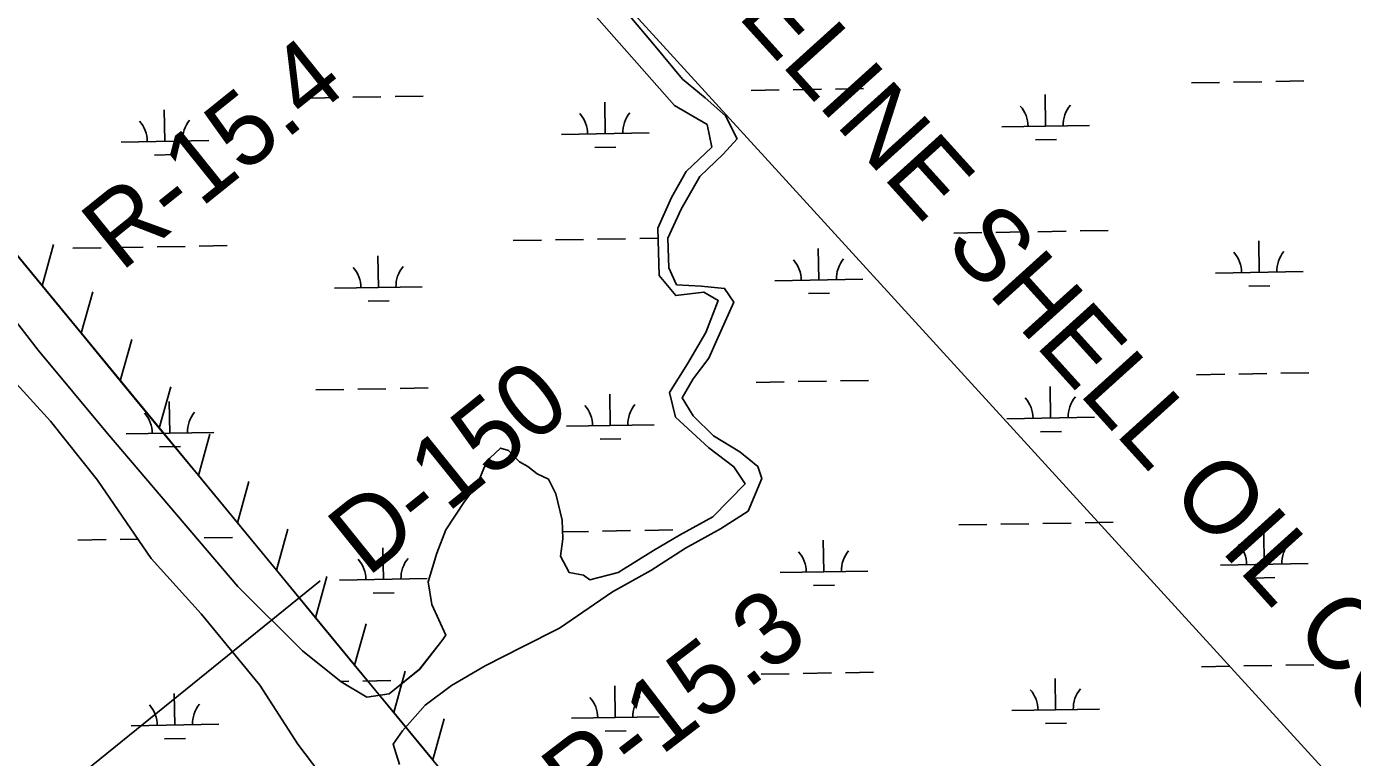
# Model space of a CAD drawing. Extents: x 3887375 to 3925618, y 296674 to 322633.
# Drawn here: x 3899931 to 3901441, y 308942 to 309775 of the extents above; entities that cross this region are included whole.
import ezdxf

# ---------------------------------------------------------------- set-up
doc = ezdxf.new("R2010")
doc.units = 0
for name, color, linetype in [('V-RIVR-EDGE', 7, 'Continuous'), ('V-RIVR-RANG', 7, 'Continuous'), ('V-RIVR-RANG-IDEN', 7, 'Continuous'), ('V-RRAP-FSHR', 7, 'Continuous'), ('V-TOPO-SHOR', 7, 'Continuous'), ('V-UTIL-IDEN', 7, 'Continuous'), ('V-UTIL-LINE', 7, 'Continuous'), ('V-WETL-SWMP', 7, 'Continuous')]:
    doc.layers.add(name, color=color, linetype=linetype)

msp = doc.modelspace()

# ---------------------------------------------------------------- linework, layer by layer
at = {"layer": 'V-RIVR-EDGE'}
msp.add_spline([(3894498, 310522.4), (3894530, 310496.1), (3894553.8, 310474.7), (3894579.9, 310451.3), (3894614.8, 310419.2), (3894633.2, 310400.7), (3894662.8, 310372.4), (3894685.1, 310353.4), (3894692.4, 310347.1), (3894709.8, 310328.1), (3894746.6, 310285.3), (3894785.8, 310252.2), (3894809.6, 310225.9), (3894830.4, 310205.4), (3894852.7, 310189.9), (3894866.7, 310171.8), (3894915.2, 310120.3), (3894950.1, 310083.7), (3894971.4, 310062.8), (3894999, 310039.4), (3895025.2, 310017), (3895052.8, 309992.7), (3895093, 309952.3), (3895110.9, 309932.8), (3895141.4, 309903.1), (3895188.9, 309855.9), (3895222.8, 309821.3), (3895255.8, 309784.3), (3895319.2, 309722.5), (3895350.7, 309688.4), (3895358.4, 309676.3), (3895364.7, 309669.4), (3895374.9, 309663.1), (3895389, 309650.4), (3895410.8, 309628.1), (3895448.5, 309583.3), (3895480.5, 309554.1), (3895503.8, 309527.8), (3895533.8, 309499.5), (3895577.4, 309454.8), (3895606.9, 309425.5), (3895653.5, 309378.8), (3895685.9, 309349.1), (3895719.8, 309314.5), (3895749.4, 309285.8), (3895790.6, 309242.5), (3895837.1, 309195.8), (3895863.7, 309164.1), (3895900, 309127.6), (3895944.1, 309081.4), (3895955.7, 309070.7), (3895974.6, 309054.6), (3896002.3, 309033.1), (3896032.8, 309003.9), (3896062.8, 308972.3), (3896082.7, 308950.4), (3896119.5, 308911.9), (3896139.3, 308892.5), (3896152, 308889.5), (3896163.1, 308883.7), (3896167.9, 308873.9), (3896170.3, 308862.3), (3896184.4, 308844.3), (3896211, 308816), (3896224.1, 308810.2), (3896236.7, 308802.4), (3896249.8, 308786.8), (3896255.6, 308776.6), (3896270.6, 308766.4), (3896280.3, 308753.2), (3896295.8, 308737.2), (3896375.3, 308661.2), (3896425.2, 308610.1), (3896464.4, 308570.6), (3896519.6, 308515.6), (3896548.7, 308483), (3896563.2, 308467.5), (3896597.6, 308430.9), (3896635.9, 308396.4), (3896666.4, 308365.7), (3896681.4, 308349.6), (3896712.4, 308320.4), (3896746.3, 308287.3), (3896777.4, 308260), (3896801.6, 308235.7), (3896820.5, 308215.3), (3896842.8, 308195.3), (3896851.5, 308181.2), (3896882.5, 308148.6), (3896918.8, 308116.4), (3896962.9, 308074.6), (3896997.8, 308033.2), (3897029.2, 307998.6), (3897042.3, 307985), (3897083.5, 307945.6), (3897107.2, 307918.3), (3897123.2, 307898.8), (3897130, 307898.8), (3897142.1, 307893), (3897146, 307882.3), (3897149.9, 307874), (3897162.9, 307860.4), (3897188.6, 307833.1), (3897229.3, 307788.8), (3897267.6, 307752.3), (3897300.5, 307715.8), (3897334.4, 307680.3), (3897361.5, 307651.1), (3897384.8, 307628.2), (3897411.4, 307599), (3897445.8, 307563.4), (3897494.3, 307516.7), (3897543.2, 307462.7), (3897584.8, 307418.4), (3897609, 307394), (3897646.8, 307355.6), (3897678.8, 307323.9), (3897715.1, 307290.3), (3897752, 307253.3), (3897767, 307236.3), (3897837.7, 307158.4), (3897886.6, 307104.4), (3897936, 307048.4), (3897965.5, 307015.3), (3898010.6, 306970.1), (3898027.5, 306949.1), (3898045, 306936), (3898063.9, 306914.1), (3898089, 306882.5), (3898117.1, 306854.7), (3898160.2, 306801.2), (3898195.6, 306763.7), (3898235.8, 306719.9), (3898261.5, 306693.6), (3898297.3, 306650.8), (3898332.7, 306612.3), (3898369.9, 306568), (3898397.5, 306534.9), (3898422.2, 306505.8), (3898462.9, 306455.1), (3898495.3, 306417.2), (3898522, 306382.2), (3898601.4, 306284.3), (3898652.2, 306228.4), (3898693.4, 306177.3), (3898729.7, 306130.6), (3898777.1, 306074.1), (3898825.5, 306014.3), (3898848.8, 305986), (3898904, 305917.4), (3898957.2, 305854.7), (3898984.4, 305818.2), (3899049.7, 305744.7), (3899107.8, 305679.4), (3899129.1, 305651.7), (3899142.7, 305630.3), (3899156.2, 305611.8), (3899175.1, 305588), (3899224, 305529.6), (3899256, 305493.6), (3899288.9, 305449.3), (3899312.6, 305415.2), (3899375.6, 305336.9), (3899410.9, 305296), (3899442.8, 305252.2), (3899470.4, 305211.9), (3899531.4, 305133.5), (3899579.3, 305071.2), (3899616.1, 305026), (3899647.1, 304986.1), (3899690.7, 304931.1), (3899729.4, 304876.6), (3899753.6, 304846.9), (3899770.6, 304821.6), (3899817.5, 304755.5), (3899845.6, 304713.2), (3899868.3, 304677.2), (3899889.6, 304650.4), (3899911.4, 304623.6), (3899955.4, 304569.1), (3899987.4, 304526.8), (3900012.6, 304494.2), (3900025.6, 304476.2), (3900037.2, 304456.8), (3900061.9, 304431.9), (3900070.7, 304424.1), (3900074.5, 304414.4), (3900075, 304404.2), (3900073, 304397.9), (3900071.5, 304388.7), (3900071.5, 304383.8), (3900075.9, 304379), (3900087.1, 304374.1), (3900096.3, 304367.7), (3900108.4, 304362.4), (3900117.1, 304353.6), (3900140.8, 304326.3), (3900165.5, 304299.1), (3900226.1, 304227.6), (3900277.9, 304164.3), (3900320, 304105.9), (3900352.4, 304062.6), (3900384.4, 304023.2), (3900411.5, 303988.2), (3900438.1, 303954.1), (3900462.8, 303926.8), (3900556.2, 303812.5), (3900597.9, 303762.9), (3900633.7, 303716.6), (3900652.6, 303691.3), (3900702, 303626.6), (3900774.6, 303530.8), (3900849.1, 303437.3), (3900903.4, 303371.2), (3900928.1, 303343.4), (3900948.9, 303317.6), (3901001.2, 303258.3), (3901038.9, 303216.9), (3901074.8, 303173.1), (3901092.2, 303147.3), (3901171.6, 303050.5), (3901205, 303008.6), (3901238.4, 302968.2), (3901274.7, 302927.8), (3901303.3, 302893.8), (3901344, 302847.5), (3901366.7, 302816.4), (3901404.5, 302770.2), (3901454.4, 302715.2), (3901507.2, 302659.2), (3901551.7, 302608.1), (3901584.7, 302570.6), (3901650, 302491.3), (3901681, 302443.6), (3901717.8, 302388.2), (3901785.5, 302298.2), (3901789.5, 302293.3)], degree=3, dxfattribs=at)
at = {"layer": 'V-RIVR-RANG'}
msp.add_line((3900265, 309143), (3899705.3, 308690.1), dxfattribs=at)
at = {"layer": 'V-RRAP-FSHR'}
for p, q in [((3899948.3, 309479.1), (3899961.4, 309526.2)), ((3899992.8, 309425.1), (3900005.9, 309472.2)), ((3900037.3, 309371.1), (3900050.4, 309418.1)), ((3900081.8, 309317.1), (3900094.9, 309364.1)), ((3900126.3, 309263), (3900139.4, 309310.1)), ((3900170.9, 309209), (3900183.9, 309256.1)), ((3900215.4, 309155), (3900228.4, 309202)), ((3900259.9, 309101), (3900272.9, 309148)), ((3900304.4, 309046.9), (3900317.4, 309094)), ((3900348.9, 308992.9), (3900362, 309040)), ((3900393.4, 308938.9), (3900406.5, 308985.9))]:
    msp.add_line(p, q, dxfattribs=at)
for points in [[(3902123.5, 306879.9), (3901073.9, 308142.8), (3900480.6, 308833), (3899865, 309580.3), (3899505.1, 310045.3), (3899437, 310117.8), (3899355, 310202.3), (3899230.8, 310321), (3898588.3, 310939.4), (3897940.3, 311570.7), (3897542.6, 311965.2), (3897487.1, 312022.6), (3897399.6, 312066), (3897286.1, 312022.4), (3897238.5, 312014.2), (3897186.3, 312049), (3896800.6, 312251.7)], [(3899948.3, 309479.1), (3899903.8, 309533.2)], [(3900037.3, 309371.1), (3899992.8, 309425.1), (3899948.3, 309479.1)], [(3900081.8, 309317.1), (3900037.3, 309371.1)], [(3900126.3, 309263), (3900081.8, 309317.1)], [(3900170.9, 309209), (3900126.3, 309263)], [(3900215.4, 309155), (3900170.9, 309209)], [(3900259.9, 309101), (3900215.4, 309155)], [(3900304.4, 309046.9), (3900259.9, 309101)], [(3900348.9, 308992.9), (3900304.4, 309046.9)], [(3900393.4, 308938.9), (3900348.9, 308992.9)]]:
    msp.add_lwpolyline(points, dxfattribs=at)
at = {"layer": 'V-TOPO-SHOR'}
for points in [[(3899864.3, 309508.2), (3899943.9, 309405.8), (3900022.7, 309310.9), (3900171.2, 309136.7), (3900244.8, 309063.2), (3900289.2, 309027.9), (3900318.3, 309010.4), (3900343.9, 309014.2), (3900378.5, 309042.4), (3900403.7, 309074.5), (3900408.2, 309081.1), (3900392.2, 309116.2), (3900388.1, 309141.7), (3900398.2, 309174.7), (3900408.2, 309201), (3900429.7, 309233.5), (3900444.2, 309252.3), (3900451.9, 309272.3), (3900458.6, 309282.8), (3900470.6, 309294.3), (3900479.7, 309291.7), (3900492.1, 309278.7), (3900501.6, 309273.4), (3900512.4, 309264.8), (3900525.3, 309259), (3900533.6, 309242), (3900541, 309212), (3900541.5, 309191), (3900539.1, 309171.2), (3900549, 309152.4), (3900565.1, 309149.6), (3900572.3, 309144.3), (3900604.5, 309152.5), (3900644.8, 309177.6), (3900674.7, 309195), (3900712.4, 309215.9), (3900749.4, 309253.5), (3900736.5, 309273.1), (3900708.1, 309294.5), (3900670, 309329.7), (3900663.3, 309357.6), (3900683.7, 309390.2), (3900704.4, 309426.1), (3900718.7, 309462.6), (3900702.3, 309471.9), (3900670.3, 309468.1), (3900651.4, 309491.1), (3900649.9, 309544.9), (3900665.4, 309579.7), (3900682, 309609.6), (3900711.5, 309637.4), (3900706.1, 309663), (3900668.7, 309684.8), (3900557.1, 309811.6)], [(3900591.1, 309818.7), (3900644.8, 309754.5), (3900678, 309714.7), (3900703.8, 309693.3), (3900727, 309672.8), (3900740.2, 309646.7), (3900724.5, 309629.3), (3900697.9, 309603.8), (3900676.3, 309566.6), (3900661.3, 309533.7), (3900662.4, 309499.8), (3900671.3, 309480.5), (3900699.3, 309478.9), (3900726, 309476.3), (3900736.4, 309460.6), (3900716.6, 309416.7), (3900708.1, 309396.8), (3900690.2, 309373.3), (3900677.5, 309351.5), (3900690, 309331), (3900713.3, 309308.1), (3900743.5, 309290), (3900764, 309273.3), (3900768.3, 309259.5), (3900752.7, 309222.5), (3900721.3, 309202.3), (3900681.4, 309180.2), (3900641.9, 309154.9), (3900598.2, 309130.4), (3900538, 309089.2), (3900495.8, 309067.7), (3900453.3, 309046.1), (3900414.9, 309023.6), (3900384.8, 309001.3), (3900358.9, 308972), (3900348.3, 308956.7), (3900355.4, 308933.6)], [(3900072.6, 309168.6), (3900011.2, 309257.7), (3899957.7, 309325), (3899888, 309401.5)], [(3900289.7, 308890.9), (3900239.6, 308956.7), (3900196.2, 309024.3), (3900129.6, 309105.4), (3900072.6, 309168.6)]]:
    msp.add_lwpolyline(points, dxfattribs=at)
at = {"layer": 'V-UTIL-LINE'}
msp.add_lwpolyline([(3891385.6, 317757.3), (3896110, 314731.3), (3903763.5, 306349.6), (3906680.6, 302364)], dxfattribs=at)
at = {"layer": 'V-WETL-SWMP'}
for p, q in [((3900756.2, 309701.8), (3900788.2, 309702.4)), ((3900804.2, 309702.7), (3900836.2, 309703.2)), ((3900852.2, 309703.5), (3900884.2, 309704)), ((3901258.1, 309710.5), (3901290, 309711)), ((3901306, 309711.3), (3901338, 309711.8)), ((3901354, 309712.1), (3901386, 309712.7)), ((3900254.4, 309693.2), (3900286.4, 309693.8)), ((3900302.4, 309694.1), (3900334.4, 309694.6)), ((3900350.4, 309694.9), (3900382.4, 309695.4)), ((3900590, 309652.6), (3900589.4, 309688.5)), ((3901091.8, 309661.2), (3901091.2, 309697.2)), ((3900088.1, 309643.9), (3900087.5, 309679.9)), ((3900540, 309651.7), (3900640, 309653.4)), ((3901041.8, 309660.3), (3901141.8, 309662)), ((3900038.2, 309643.1), (3900138.1, 309644.8)), ((3901080.1, 309645.5), (3901104.1, 309645.9)), ((3900076.4, 309628.3), (3900100.4, 309628.7)), ((3900578.2, 309636.9), (3900602.2, 309637.3)), ((3900533.2, 309531.5), (3900565.2, 309532)), ((3900581.2, 309532.3), (3900613.2, 309532.9)), ((3900629.2, 309533.1), (3900650.2, 309533.5)), ((3900987, 309539.3), (3901019, 309539.8)), ((3901035, 309540.1), (3901067, 309540.7)), ((3901083, 309540.9), (3901115, 309541.5)), ((3901131, 309541.7), (3901163, 309542.3)), ((3899983.4, 309522.1), (3900015.4, 309522.6)), ((3900031.4, 309522.9), (3900063.4, 309523.4)), ((3900079.4, 309523.7), (3900111.4, 309524.2)), ((3900127.4, 309524.5), (3900159.3, 309525.1)), ((3900485.2, 309530.7), (3900517.2, 309531.2)), ((3900833.3, 309485.9), (3900832.7, 309521.9)), ((3901335.2, 309494.5), (3901334.6, 309530.5)), ((3900331.5, 309477.3), (3900330.9, 309513.3)), ((3900783.4, 309485), (3900883.3, 309486.7)), ((3901285.2, 309493.6), (3901385.2, 309495.4)), ((3900281.5, 309476.4), (3900381.5, 309478.1)), ((3901323.4, 309478.9), (3901347.4, 309479.3)), ((3900319.8, 309461.6), (3900343.8, 309462.1)), ((3900821.6, 309470.3), (3900845.6, 309470.7)), ((3900761.9, 309369.2), (3900793.9, 309369.8)), ((3900809.9, 309370), (3900841.9, 309370.6)), ((3900857.9, 309370.9), (3900889.9, 309371.4)), ((3901263.8, 309377.8), (3901295.8, 309378.4)), ((3901311.8, 309378.7), (3901343.7, 309379.2)), ((3901359.7, 309379.5), (3901391.7, 309380)), ((3900260.1, 309360.6), (3900292.1, 309361.2)), ((3900308.1, 309361.4), (3900340.1, 309362)), ((3900356.1, 309362.2), (3900388.1, 309362.8)), ((3900595.7, 309319.9), (3900595.1, 309355.9)), ((3901097.5, 309328.5), (3901096.9, 309364.5)), ((3900093.9, 309311.3), (3900093.2, 309347.3)), ((3900545.7, 309319.1), (3900645.7, 309320.8)), ((3901047.5, 309327.7), (3901147.5, 309329.4)), ((3900043.9, 309310.5), (3900143.8, 309312.2)), ((3901085.8, 309312.9), (3901109.8, 309313.3)), ((3900082.1, 309295.7), (3900106.1, 309296.1)), ((3900584, 309304.3), (3900607.9, 309304.7)), ((3900541.3, 309198.9), (3900570.9, 309199.4)), ((3900586.9, 309199.7), (3900618.9, 309200.2)), ((3900634.9, 309200.5), (3900666.9, 309201.1)), ((3900992.8, 309206.7), (3901024.7, 309207.2)), ((3901040.7, 309207.5), (3901072.7, 309208)), ((3901088.7, 309208.3), (3901120.7, 309208.8)), ((3901136.7, 309209.1), (3901168.7, 309209.7)), ((3899989.1, 309189.4), (3900021.1, 309190)), ((3900037.1, 309190.2), (3900057.5, 309190.6)), ((3900133.1, 309191.9), (3900165.1, 309192.4)), ((3900839.1, 309153.3), (3900838.4, 309189.3)), ((3901340.9, 309161.9), (3901340.3, 309197.9)), ((3900337.2, 309144.7), (3900336.6, 309180.6)), ((3900789.1, 309152.4), (3900889, 309154.1)), ((3901290.9, 309161), (3901390.9, 309162.7)), ((3900287.2, 309143.8), (3900387.2, 309145.5)), ((3901329.2, 309146.2), (3901353.1, 309146.7)), ((3900325.5, 309129), (3900349.5, 309129.4)), ((3900827.3, 309137.6), (3900851.3, 309138)), ((3900767.6, 309036.6), (3900799.6, 309037.1)), ((3900815.6, 309037.4), (3900847.6, 309038)), ((3900863.6, 309038.2), (3900895.6, 309038.8)), ((3901269.5, 309045.2), (3901301.5, 309045.8)), ((3901317.5, 309046), (3901349.5, 309046.6)), ((3901365.5, 309046.9), (3901397.5, 309047.4)), ((3900288.7, 309028.4), (3900297.8, 309028.5)), ((3900313.8, 309028.8), (3900345.8, 309029.3)), ((3900361.8, 309029.6), (3900362.8, 309029.6)), ((3900601.4, 308987.3), (3900600.8, 309023.3)), ((3901103.2, 308995.9), (3901102.6, 309031.9)), ((3900099.6, 308978.7), (3900098.9, 309014.7)), ((3900551.4, 308986.4), (3900651.4, 308988.2)), ((3901053.2, 308995.1), (3901153.2, 308996.8)), ((3900049.6, 308977.8), (3900149.6, 308979.5)), ((3901091.5, 308980.3), (3901115.5, 308980.7)), ((3900087.8, 308963.1), (3900111.8, 308963.5)), ((3900589.7, 308971.7), (3900613.7, 308972.1))]:
    msp.add_line(p, q, dxfattribs=at)
for points in [[(3900557.1, 309811.6), (3900668.7, 309684.8), (3900706.1, 309663), (3900711.5, 309637.4), (3900682, 309609.6), (3900665.4, 309579.7), (3900649.9, 309544.9), (3900651.4, 309491.1), (3900670.3, 309468.1), (3900702.3, 309471.9), (3900718.7, 309462.6), (3900704.4, 309426.1), (3900683.7, 309390.2), (3900663.3, 309357.6), (3900670, 309329.7), (3900708.1, 309294.5), (3900736.5, 309273.1), (3900749.4, 309253.5), (3900712.4, 309215.9), (3900674.7, 309195), (3900644.8, 309177.6), (3900604.5, 309152.5), (3900572.3, 309144.3), (3900565.1, 309149.6), (3900549, 309152.4), (3900539.1, 309171.2), (3900541.5, 309191), (3900541, 309212), (3900533.6, 309242), (3900525.3, 309259), (3900512.4, 309264.8), (3900501.6, 309273.4), (3900492.1, 309278.7), (3900479.7, 309291.7), (3900470.6, 309294.3), (3900458.6, 309282.8), (3900451.9, 309272.3), (3900444.2, 309252.3), (3900429.7, 309233.5), (3900408.2, 309201), (3900398.2, 309174.7), (3900388.1, 309141.7), (3900392.2, 309116.2), (3900408.2, 309081.1), (3900403.7, 309074.5), (3900378.4, 309042.4), (3900343.9, 309014.2), (3900318.3, 309010.4), (3900289.2, 309027.9), (3900244.8, 309063.2), (3900171.2, 309136.7), (3900022.7, 309310.9), (3899943.9, 309405.8), (3899864.3, 309508.2)], [(3900355.4, 308933.6), (3900348.3, 308956.7), (3900358.9, 308972), (3900384.8, 309001.3), (3900414.9, 309023.6), (3900453.3, 309046.1), (3900495.8, 309067.7), (3900538, 309089.2), (3900598.2, 309130.4), (3900641.9, 309154.9), (3900681.4, 309180.2), (3900721.3, 309202.3), (3900752.7, 309222.5), (3900768.3, 309259.5), (3900764, 309273.3), (3900743.5, 309290), (3900713.3, 309308.1), (3900690, 309331), (3900677.5, 309351.5), (3900690.2, 309373.3), (3900708.1, 309396.8), (3900716.6, 309416.7), (3900736.4, 309460.6), (3900726, 309476.3), (3900699.3, 309478.9), (3900671.3, 309480.5), (3900662.4, 309499.8), (3900661.3, 309533.7), (3900676.3, 309566.6), (3900697.9, 309603.8), (3900724.5, 309629.3), (3900740.2, 309646.7), (3900727, 309672.8), (3900703.8, 309693.3), (3900678, 309714.7), (3900644.8, 309754.5), (3900591.1, 309818.7)], [(3899827, 309498.6), (3899855.8, 309450.1), (3899888, 309401.5), (3899957.7, 309325), (3900011.2, 309257.7), (3900072.6, 309168.6), (3900129.6, 309105.4), (3900196.2, 309024.3), (3900239.6, 308956.7), (3900289.7, 308890.9)]]:
    msp.add_lwpolyline(points, dxfattribs=at)
for centre, start, end in [((3901036.6, 309660.7), 0.2115, 41.7552), ((3901147, 309662.6), 140.2115, 181.7552), ((3900143.4, 309645.4), 140.2115, 181.7552), ((3900534.7, 309652.1), 0.2115, 41.7552), ((3900645.2, 309654), 140.2115, 181.7552), ((3900032.9, 309643.5), 0.2115, 41.7552), ((3901279.9, 309494), 0.2115, 41.7552), ((3901390.4, 309495.9), 140.2115, 181.7552), ((3900778.1, 309485.4), 0.2115, 41.7552), ((3900888.6, 309487.3), 140.2115, 181.7552), ((3900276.3, 309476.8), 0.2115, 41.7552), ((3900386.7, 309478.7), 140.2115, 181.7552), ((3901042.3, 309328.1), 0.2115, 41.7552), ((3901152.7, 309330), 140.2115, 181.7552), ((3900149.1, 309312.7), 140.2115, 181.7552), ((3900540.4, 309319.5), 0.2115, 41.7552), ((3900650.9, 309321.3), 140.2115, 181.7552), ((3900038.6, 309310.8), 0.2115, 41.7552), ((3901285.6, 309161.4), 0.2115, 41.7552), ((3901396.1, 309163.3), 140.2115, 181.7552), ((3900783.8, 309152.8), 0.2115, 41.7552), ((3900894.3, 309154.7), 140.2115, 181.7552), ((3900282, 309144.2), 0.2115, 41.7552), ((3900392.4, 309146.1), 140.2115, 181.7552), ((3901048, 308995.4), 0.2115, 41.7552), ((3901158.5, 308997.3), 140.2115, 181.7552), ((3900546.2, 308986.8), 0.2115, 41.7552), ((3900656.6, 308988.7), 140.2115, 181.7552), ((3900044.3, 308978.2), 0.2115, 41.7552), ((3900154.8, 308980.1), 140.2115, 181.7552)]:
    msp.add_arc(centre, 35.2, start, end, dxfattribs=at)

# ---------------------------------------------------------------- texts
at = {"layer": 'V-RIVR-RANG-IDEN'}
for s, rotation, p in [('R-15.4', 38.791, (3900038, 309494.2)), ('D-150', 38.8313, (3900318.9, 309146.4)), ('R-15.3', 37.5216, (3900560.5, 308871.6))]:
    msp.add_text(s, height=83, rotation=rotation, dxfattribs=at).set_placement(p)
at = {"layer": 'V-UTIL-IDEN'}
msp.add_text('1-16" OIL PIPELINE SHELL OIL CO.', height=83, rotation=312.1245, dxfattribs=at).set_placement((3900282.6, 310291.7))

doc.saveas('drawing.dxf')
